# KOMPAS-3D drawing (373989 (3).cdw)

Referenced files in C:\Documents and Settings\оля\Мои документы\чертежи\: Трехкулачковый патрон.frw
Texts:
  Текст на чертеже
  Размерные надписи
  Шероховатость
  Линия-выноска #1
  Линия-выноска #2
  Линия-выноска #3
  Отклонения формы и база
  Заголовок таблицы
  Ячейка таблицы
  Стрелка вида
  Обозначение изменения
  Фигурная скобка
  Номер узла
  Марка координационной оси
  VRCB
  Выносная надпись
  Обозначение узла
  Марка/позиционное обозначение с линией-выноской
  Марка/позиционное обозначение на линии
  Марка/позиционное обозначение без линии-выноски
  Упор
  Оля
  Изм. Лист № докум      Подпись      Дата
  Дублик
  Взамен
  Подпись
  Изм.
  Лист
  № докумен.
  Дата
  ТС-51.60240
  СК-4.54.60640
  Операция 05. Токарная
  Установ А
  Установ Б
  Rz20
Dimensions and other numbers on the sheet: 7; 1; 42,5; 70,19; 2; 38; 1:1; 0; 3; 4; 5; 6; 8; 9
